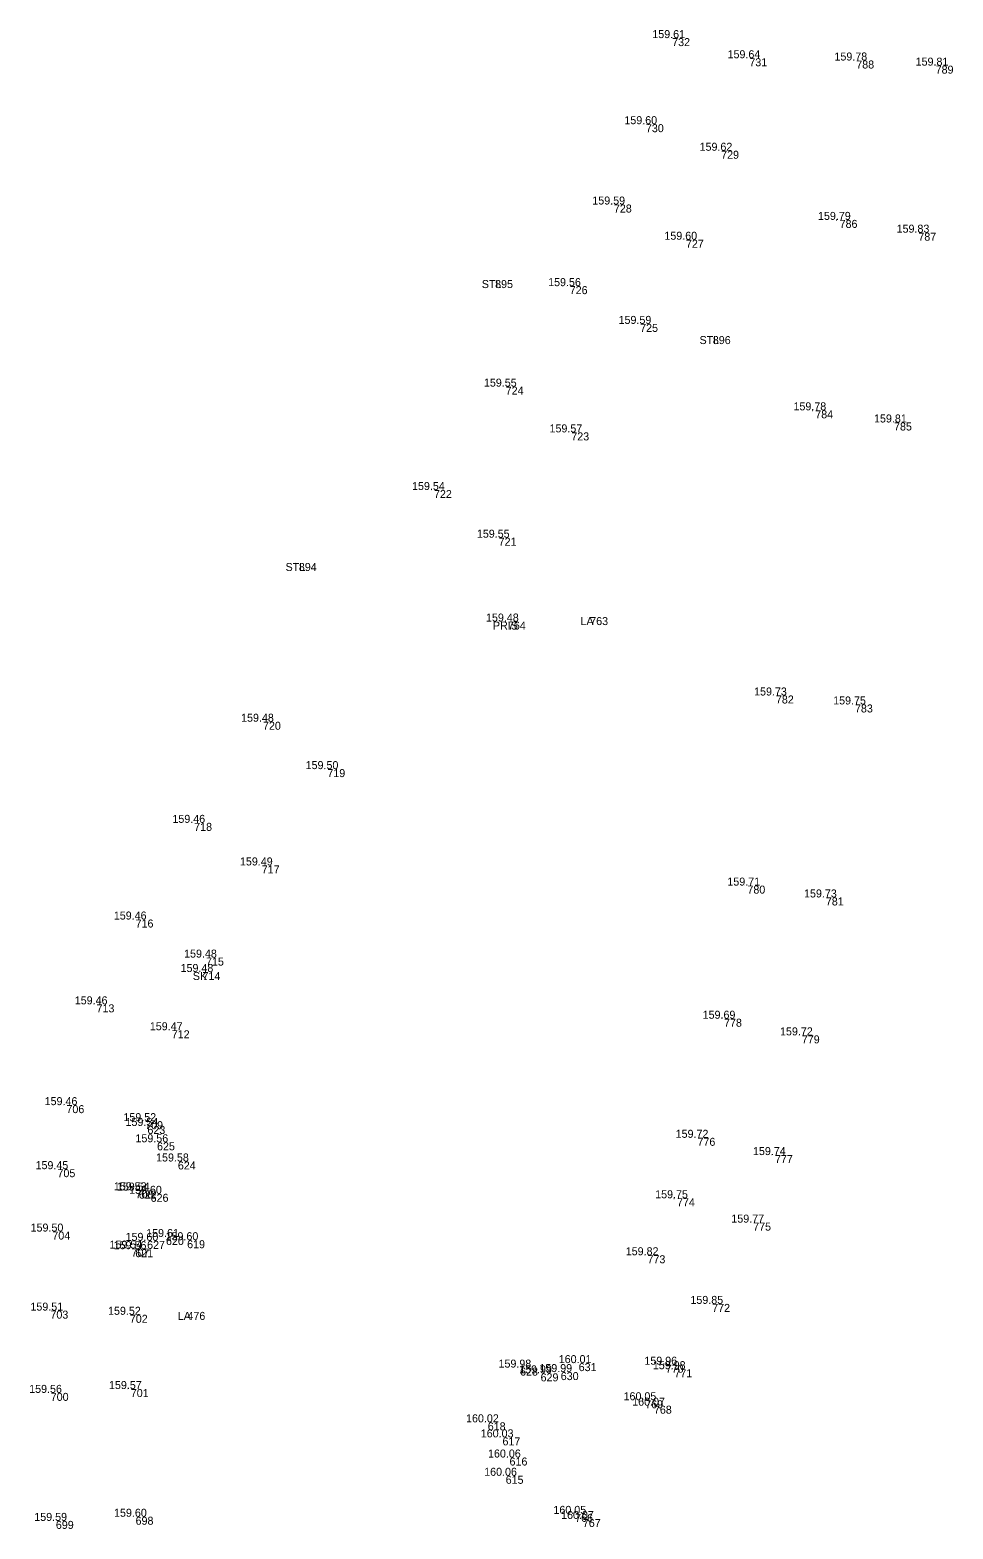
# Model space of a CAD drawing. Extents: x -583198 to -582878, y -1211024 to -1210637.
# Drawn here: x -582908.23 to -582879.4, y -1210783.85 to -1210737.02 of the extents above; entities that cross this region are included whole.
import ezdxf

# ---------------------------------------------------------------- set-up
doc = ezdxf.new("R2010")
doc.units = 0
for name, color, linetype in [('1   Kódy', 7, 'Continuous'), ('4   Body podrobné', 7, 'Continuous'), ('5   Body podrobné - čísla', 7, 'Continuous'), ('6   Body podrobné - výšky', 7, 'Continuous')]:
    doc.layers.add(name, color=color, linetype=linetype)

msp = doc.modelspace()

# ---------------------------------------------------------------- linework, layer by layer
at = {"layer": '4   Body podrobné'}
for p, q in [((-582888.26, -1210737.27), (-582888.259, -1210737.27)), ((-582885.85, -1210737.9), (-582885.849, -1210737.9)), ((-582882.51, -1210737.97), (-582882.509, -1210737.97)), ((-582880.03, -1210738.13), (-582880.029, -1210738.13)), ((-582889.08, -1210739.96), (-582889.079, -1210739.96)), ((-582886.73, -1210740.79), (-582886.729, -1210740.79)), ((-582890.08, -1210742.47), (-582890.079, -1210742.47)), ((-582883.03, -1210742.95), (-582883.029, -1210742.95)), ((-582880.57, -1210743.35), (-582880.569, -1210743.35)), ((-582887.83, -1210743.57), (-582887.829, -1210743.57)), ((-582893.79, -1210744.83), (-582893.789, -1210744.83)), ((-582891.46, -1210745.02), (-582891.459, -1210745.02)), ((-582889.26, -1210746.2), (-582889.259, -1210746.2)), ((-582886.99, -1210746.58), (-582886.989, -1210746.58)), ((-582893.46, -1210748.16), (-582893.459, -1210748.16)), ((-582883.79, -1210748.9), (-582883.789, -1210748.9)), ((-582891.41, -1210749.59), (-582891.409, -1210749.59)), ((-582881.33, -1210749.28), (-582881.329, -1210749.28)), ((-582895.7, -1210751.39), (-582895.699, -1210751.39)), ((-582893.68, -1210752.88), (-582893.679, -1210752.88)), ((-582899.92, -1210753.67), (-582899.919, -1210753.67)), ((-582893.39, -1210755.5), (-582893.389, -1210755.5)), ((-582890.82, -1210755.36), (-582890.819, -1210755.36)), ((-582885.02, -1210757.81), (-582885.019, -1210757.81)), ((-582882.55, -1210758.09), (-582882.549, -1210758.09)), ((-582901.04, -1210758.63), (-582901.039, -1210758.63)), ((-582899.03, -1210760.11), (-582899.029, -1210760.11)), ((-582903.19, -1210761.79), (-582903.189, -1210761.79)), ((-582901.08, -1210763.12), (-582901.079, -1210763.12)), ((-582885.91, -1210763.75), (-582885.909, -1210763.75)), ((-582883.46, -1210764.12), (-582883.459, -1210764.12)), ((-582905.02, -1210764.81), (-582905.019, -1210764.81)), ((-582902.82, -1210766), (-582902.819, -1210766)), ((-582902.93, -1210766.45), (-582902.929, -1210766.45)), ((-582906.24, -1210767.46), (-582906.239, -1210767.46)), ((-582903.89, -1210768.27), (-582903.889, -1210768.27)), ((-582886.64, -1210767.91), (-582886.639, -1210767.91)), ((-582884.21, -1210768.43), (-582884.209, -1210768.43)), ((-582907.18, -1210770.61), (-582907.179, -1210770.61)), ((-582904.72, -1210771.11), (-582904.719, -1210771.11)), ((-582904.65, -1210771.26), (-582904.649, -1210771.26)), ((-582887.47, -1210771.63), (-582887.469, -1210771.63)), ((-582904.35, -1210771.77), (-582904.349, -1210771.77)), ((-582903.7, -1210772.37), (-582903.699, -1210772.37)), ((-582885.05, -1210772.17), (-582885.049, -1210772.17)), ((-582907.46, -1210772.61), (-582907.459, -1210772.61)), ((-582905.02, -1210773.27), (-582905.019, -1210773.27)), ((-582904.92, -1210773.28), (-582904.919, -1210773.28)), ((-582904.55, -1210773.38), (-582904.549, -1210773.38)), ((-582888.11, -1210773.52), (-582888.109, -1210773.52)), ((-582885.73, -1210774.28), (-582885.729, -1210774.28)), ((-582907.62, -1210774.56), (-582907.619, -1210774.56)), ((-582904.66, -1210774.85), (-582904.659, -1210774.85)), ((-582904.07, -1210774.73), (-582904.069, -1210774.73)), ((-582903.41, -1210774.83), (-582903.409, -1210774.83)), ((-582905.15, -1210775.09), (-582905.149, -1210775.09)), ((-582905.03, -1210775.11), (-582905.029, -1210775.11)), ((-582889.03, -1210775.3), (-582889.029, -1210775.3)), ((-582907.68, -1210777.03), (-582907.679, -1210777.03)), ((-582905.2, -1210777.16), (-582905.199, -1210777.16)), ((-582903.4, -1210777.07), (-582903.399, -1210777.07)), ((-582887.01, -1210776.82), (-582887.009, -1210776.82)), ((-582891.18, -1210778.67), (-582891.179, -1210778.67)), ((-582893.01, -1210778.81), (-582893.009, -1210778.81)), ((-582892.37, -1210778.99), (-582892.369, -1210778.99)), ((-582891.74, -1210778.95), (-582891.739, -1210778.95)), ((-582888.46, -1210778.72), (-582888.459, -1210778.72)), ((-582888.19, -1210778.86), (-582888.189, -1210778.86)), ((-582907.67, -1210779.6), (-582907.669, -1210779.6)), ((-582905.17, -1210779.48), (-582905.169, -1210779.48)), ((-582889.1, -1210779.83), (-582889.099, -1210779.83)), ((-582888.83, -1210780), (-582888.829, -1210780)), ((-582894.02, -1210780.52), (-582894.019, -1210780.52)), ((-582893.56, -1210780.99), (-582893.559, -1210780.99)), ((-582893.34, -1210781.62), (-582893.339, -1210781.62)), ((-582893.46, -1210782.19), (-582893.459, -1210782.19)), ((-582907.51, -1210783.6), (-582907.509, -1210783.6)), ((-582905.02, -1210783.47), (-582905.019, -1210783.47)), ((-582891.29, -1210783.38), (-582891.289, -1210783.38)), ((-582891.05, -1210783.54), (-582891.049, -1210783.54))]:
    msp.add_line(p, q, dxfattribs=at)

# ---------------------------------------------------------------- texts
at = {"layer": '1   Kódy'}
for s, p in [('STL', (-582894.112, -1210745.08)), ('STL', (-582887.312, -1210746.83)), ('STL', (-582900.242, -1210753.92)), ('PRIS', (-582893.765, -1210755.75)), ('LA', (-582891.03, -1210755.61)), ('SK', (-582903.139, -1210766.7)), ('LA', (-582903.61, -1210777.32))]:
    msp.add_text(s, height=0.25, dxfattribs=at).set_placement(p)
at = {"layer": '5   Body podrobné - čísla'}
for s, p in [(' 732', (-582888.26, -1210737.52)), (' 731', (-582885.85, -1210738.15)), (' 788', (-582882.51, -1210738.22)), (' 789', (-582880.03, -1210738.38)), (' 730', (-582889.08, -1210740.21)), (' 729', (-582886.73, -1210741.04)), (' 728', (-582890.08, -1210742.72)), (' 786', (-582883.03, -1210743.2)), (' 787', (-582880.57, -1210743.6)), (' 727', (-582887.83, -1210743.82)), (' 895', (-582893.79, -1210745.08)), (' 726', (-582891.46, -1210745.27)), (' 725', (-582889.26, -1210746.45)), (' 896', (-582886.99, -1210746.83)), (' 724', (-582893.46, -1210748.41)), (' 784', (-582883.79, -1210749.15)), (' 723', (-582891.41, -1210749.84)), (' 785', (-582881.33, -1210749.53)), (' 722', (-582895.7, -1210751.64)), (' 721', (-582893.68, -1210753.13)), (' 894', (-582899.92, -1210753.92)), (' 764', (-582893.39, -1210755.75)), (' 763', (-582890.82, -1210755.61)), (' 782', (-582885.02, -1210758.06)), (' 783', (-582882.55, -1210758.34)), (' 720', (-582901.04, -1210758.88)), (' 719', (-582899.03, -1210760.36)), (' 718', (-582903.19, -1210762.04)), (' 717', (-582901.08, -1210763.37)), (' 780', (-582885.91, -1210764)), (' 781', (-582883.46, -1210764.37)), (' 716', (-582905.02, -1210765.06)), (' 715', (-582902.82, -1210766.25)), (' 714', (-582902.93, -1210766.7)), (' 713', (-582906.24, -1210767.71)), (' 712', (-582903.89, -1210768.52)), (' 778', (-582886.64, -1210768.16)), (' 779', (-582884.21, -1210768.68)), (' 706', (-582907.18, -1210770.86)), (' 709', (-582904.72, -1210771.36)), (' 623', (-582904.65, -1210771.51)), (' 776', (-582887.47, -1210771.88)), (' 625', (-582904.35, -1210772.02)), (' 624', (-582903.7, -1210772.62)), (' 777', (-582885.05, -1210772.42)), (' 705', (-582907.46, -1210772.86)), (' 708', (-582905.02, -1210773.52)), (' 622', (-582904.92, -1210773.53)), (' 626', (-582904.55, -1210773.63)), (' 774', (-582888.11, -1210773.77)), (' 775', (-582885.73, -1210774.53)), (' 704', (-582907.62, -1210774.81)), (' 627', (-582904.66, -1210775.1)), (' 620', (-582904.07, -1210774.98)), (' 619', (-582903.41, -1210775.08)), (' 707', (-582905.15, -1210775.34)), (' 621', (-582905.03, -1210775.36)), (' 773', (-582889.03, -1210775.55)), (' 703', (-582907.68, -1210777.28)), (' 702', (-582905.2, -1210777.41)), (' 476', (-582903.4, -1210777.32)), (' 772', (-582887.01, -1210777.07)), (' 631', (-582891.18, -1210778.92)), (' 628', (-582893.01, -1210779.06)), (' 629', (-582892.37, -1210779.24)), (' 630', (-582891.74, -1210779.2)), (' 770', (-582888.46, -1210778.97)), (' 771', (-582888.19, -1210779.11)), (' 700', (-582907.67, -1210779.85)), (' 701', (-582905.17, -1210779.73)), (' 769', (-582889.1, -1210780.08)), (' 768', (-582888.83, -1210780.25)), (' 618', (-582894.02, -1210780.77)), (' 617', (-582893.56, -1210781.24)), (' 616', (-582893.34, -1210781.87)), (' 615', (-582893.46, -1210782.44)), (' 699', (-582907.51, -1210783.85)), (' 698', (-582905.02, -1210783.72)), (' 766', (-582891.29, -1210783.63)), (' 767', (-582891.05, -1210783.79))]:
    msp.add_text(s, height=0.25, dxfattribs=at).set_placement(p)
at = {"layer": '6   Body podrobné - výšky'}
for s, p in [('159.61', (-582888.787, -1210737.27)), ('159.64', (-582886.437, -1210737.9)), ('159.78', (-582883.098, -1210737.97)), ('159.81', (-582880.562, -1210738.13)), ('159.60', (-582889.66, -1210739.96)), ('159.62', (-582887.311, -1210740.79)), ('159.59', (-582890.661, -1210742.47)), ('159.79', (-582883.612, -1210742.95)), ('159.60', (-582888.41, -1210743.57)), ('159.83', (-582881.157, -1210743.35)), ('159.56', (-582892.041, -1210745.02)), ('159.59', (-582889.841, -1210746.2)), ('159.55', (-582894.047, -1210748.16)), ('159.78', (-582884.378, -1210748.9)), ('159.81', (-582881.862, -1210749.28)), ('159.57', (-582891.998, -1210749.59)), ('159.54', (-582896.292, -1210751.39)), ('159.55', (-582894.267, -1210752.88)), ('159.48', (-582893.982, -1210755.5)), ('159.73', (-582885.608, -1210757.81)), ('159.75', (-582883.138, -1210758.09)), ('159.48', (-582901.632, -1210758.63)), ('159.50', (-582899.616, -1210760.11)), ('159.46', (-582903.777, -1210761.79)), ('159.49', (-582901.667, -1210763.12)), ('159.71', (-582886.443, -1210763.75)), ('159.73', (-582884.048, -1210764.12)), ('159.46', (-582905.607, -1210764.81)), ('159.48', (-582903.412, -1210766)), ('159.48', (-582903.522, -1210766.45)), ('159.46', (-582906.827, -1210767.46)), ('159.69', (-582887.215, -1210767.91)), ('159.47', (-582904.483, -1210768.27)), ('159.72', (-582884.798, -1210768.43)), ('159.46', (-582907.767, -1210770.61)), ('159.52', (-582905.307, -1210771.11)), ('159.54', (-582905.242, -1210771.26)), ('159.56', (-582904.931, -1210771.77)), ('159.72', (-582888.058, -1210771.63)), ('159.58', (-582904.287, -1210772.37)), ('159.74', (-582885.643, -1210772.17)), ('159.45', (-582908.052, -1210772.61)), ('159.52', (-582905.607, -1210773.27)), ('159.54', (-582905.512, -1210773.28)), ('159.60', (-582905.13, -1210773.38)), ('159.75', (-582888.698, -1210773.52)), ('159.50', (-582908.206, -1210774.56)), ('159.77', (-582886.319, -1210774.28)), ('159.54', (-582905.742, -1210775.09)), ('159.56', (-582905.611, -1210775.11)), ('159.60', (-582905.24, -1210774.85)), ('159.61', (-582904.597, -1210774.73)), ('159.60', (-582903.99, -1210774.83)), ('159.82', (-582889.617, -1210775.3)), ('159.51', (-582908.212, -1210777.03)), ('159.85', (-582887.597, -1210776.82)), ('159.52', (-582905.787, -1210777.16)), ('159.98', (-582893.591, -1210778.81)), ('160.01', (-582891.71, -1210778.67)), ('159.96', (-582889.035, -1210778.72)), ('159.98', (-582888.771, -1210778.86)), ('159.99', (-582892.945, -1210778.99)), ('159.99', (-582892.315, -1210778.95)), ('159.56', (-582908.251, -1210779.6)), ('159.57', (-582905.758, -1210779.48)), ('160.05', (-582889.685, -1210779.83)), ('160.07', (-582889.416, -1210780)), ('160.02', (-582894.605, -1210780.52)), ('160.03', (-582894.145, -1210780.99)), ('160.06', (-582893.919, -1210781.62)), ('160.06', (-582894.039, -1210782.19)), ('159.59', (-582908.091, -1210783.6)), ('159.60', (-582905.6, -1210783.47)), ('160.05', (-582891.875, -1210783.38)), ('160.07', (-582891.636, -1210783.54))]:
    msp.add_text(s, height=0.25, dxfattribs=at).set_placement(p)

doc.saveas('drawing.dxf')
